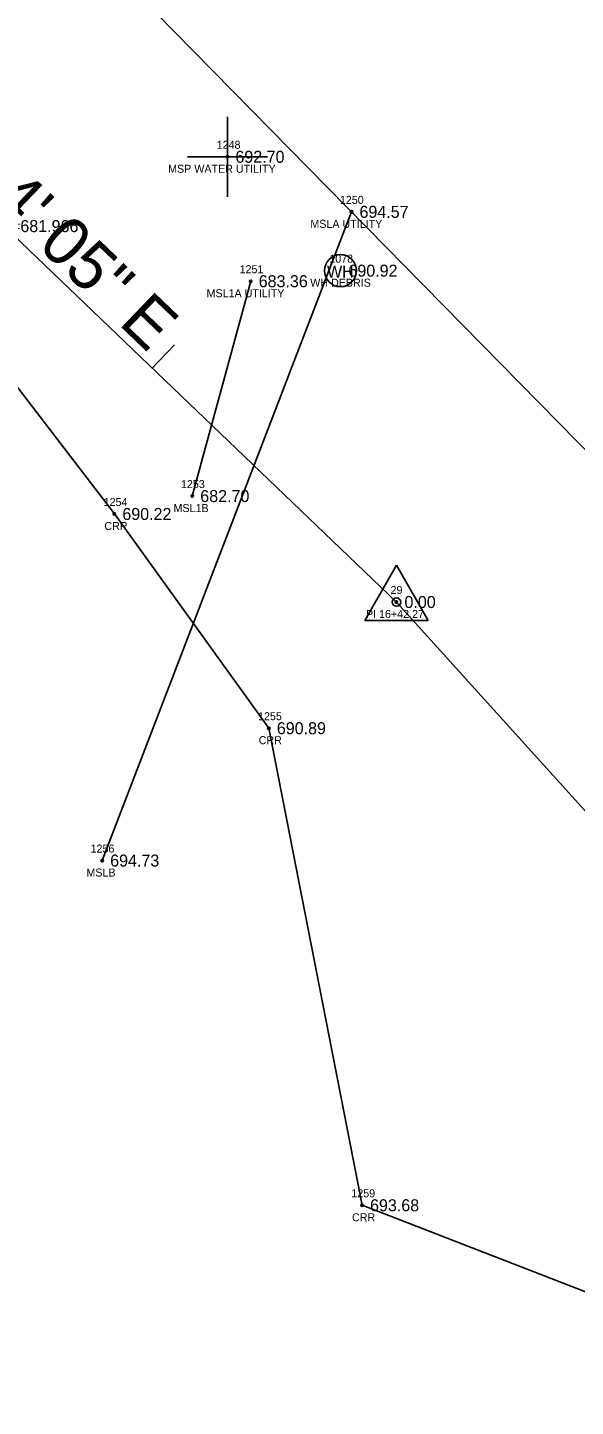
# Model space of a CAD drawing. Extents: x 1736563 to 1738032, y 1150548 to 1154248.
# Drawn here: x 1737439.5 to 1737508, y 1152510.8 to 1152683.1 of the extents above; entities that cross this region are included whole.
import ezdxf

# ---------------------------------------------------------------- set-up
doc = ezdxf.new("R2010")
doc.units = 0
for name, color, linetype in [('RD_EX_DV_PropPin', 7, 'Continuous'), ('RD_EX_H2O', 7, 'Continuous'), ('RD_EX_H2O_txCode', 7, 'Continuous'), ('RD_EX_Misc', 7, 'Continuous'), ('RD_EX_Misc_txCode', 7, 'Continuous'), ('RD_EX_SU_Misc_TxCode', 7, 'Continuous'), ('RD_EX_TX_H2O_ELEV', 7, 'Continuous'), ('RD_EX_TX_Misc_ELEV', 7, 'Continuous'), ('RD_HC_Cl', 7, 'Continuous'), ('RD_HC_Data', 7, 'Continuous'), ('RD_HC_Data_Tic', 7, 'Continuous'), ('RD_HC_Survey_ELEV', 7, 'Continuous'), ('RD_HC_txCode', 7, 'Continuous'), ('RD_SMD_Locator', 7, 'Continuous')]:
    doc.layers.add(name, color=color, linetype=linetype)

msp = doc.modelspace()

# ---------------------------------------------------------------- linework, layer by layer
at = {"layer": 'RD_EX_DV_PropPin'}
msp.add_circle((1737478.65, 1152652.71), 2, dxfattribs=at)
at = {"layer": 'RD_EX_H2O'}
for points in [[(1737441.68, 1152693.88), (1737445.94, 1152694.75), (1737513.08, 1152626.45), (1737553.92, 1152572.92), (1737629.09, 1152489.23), (1737700.8, 1152421.73), (1737779.1, 1152356.49), (1737820.92, 1152328.76)], [(1737416.87, 1152657.43), (1737429.45, 1152649.61), (1737450.39, 1152622.3), (1737469.7, 1152595.53), (1737481.35, 1152535.91), (1737513.9, 1152523.3), (1737579.93, 1152459.05), (1737654.23, 1152384.64), (1737738.06, 1152318.16), (1737784.96, 1152282.34)]]:
    msp.add_lwpolyline(points, dxfattribs=at)
at = {"layer": 'RD_EX_Misc'}
for p, q in [((1737464.52, 1152661.94), (1737464.52, 1152671.94)), ((1737459.52, 1152666.94), (1737469.52, 1152666.94)), ((1737480.03, 1152660.06), (1737448.87, 1152578.99)), ((1737467.43, 1152651.39), (1737460.13, 1152624.54))]:
    msp.add_line(p, q, dxfattribs=at)
at = {"layer": 'RD_EX_SU_Misc_TxCode'}
msp.add_circle((1737478.65, 1152652.71), 0.005, dxfattribs=at)
at = {"layer": 'RD_HC_Cl'}
for p, q in [((1737384.75, 1152707.94), (1737485.65, 1152611.3)), ((1737485.65, 1152611.3), (1737588.93, 1152496.85))]:
    msp.add_line(p, q, dxfattribs=at)
at = {"layer": 'RD_HC_Data'}
for p, q in [((1737481.68, 1152609.01), (1737485.65, 1152615.89)), ((1737485.65, 1152615.89), (1737489.62, 1152609.01)), ((1737481.68, 1152609.01), (1737489.62, 1152609.01))]:
    msp.add_line(p, q, dxfattribs=at)
msp.add_circle((1737485.65, 1152611.3), 0.529, dxfattribs=at)
at = {"layer": 'RD_HC_Data_Tic'}
msp.add_line((1737455.12, 1152640.54), (1737457.89, 1152643.43), dxfattribs=at)
at = {"layer": 'RD_SMD_Locator'}
for centre in [(1737464.52, 1152666.94), (1737480.03, 1152660.06), (1737467.43, 1152651.39), (1737460.13, 1152624.54), (1737450.39, 1152622.3), (1737485.65, 1152611.3), (1737469.7, 1152595.53), (1737448.87, 1152578.99), (1737481.35, 1152535.91)]:
    msp.add_circle(centre, 0.15, dxfattribs=at)

# ---------------------------------------------------------------- texts
at = {"layer": 'RD_EX_DV_PropPin'}
msp.add_text('WH', height=1.5, dxfattribs=at).set_placement((1737476.97, 1152651.83))
at = {"layer": 'RD_EX_H2O_txCode'}
for s, p in [('1078', (1737477.26, 1152653.71)), ('WH DEBRIS', (1737474.87, 1152650.71)), ('1254', (1737449.05, 1152623.3)), ('CRR', (1737449.14, 1152620.3)), ('1255', (1737468.35, 1152596.53)), ('CRR', (1737468.44, 1152593.53)), ('1259', (1737480.01, 1152536.91)), ('CRR', (1737480.1, 1152533.91))]:
    msp.add_text(s, height=1, dxfattribs=at).set_placement(p)
at = {"layer": 'RD_EX_Misc_txCode'}
for s, p in [('1248', (1737463.18, 1152667.94)), ('MSP WATER UTILITY', (1737457.11, 1152664.94)), ('1250', (1737478.58, 1152661.06)), ('MSLA UTILITY', (1737474.89, 1152658.06)), ('1251', (1737466.04, 1152652.39)), ('MSL1A UTILITY', (1737461.92, 1152649.39)), ('1253', (1737458.72, 1152625.54)), ('MSL1B', (1737457.79, 1152622.54)), ('1256', (1737447.42, 1152579.99)), ('MSLB', (1737446.9, 1152576.99))]:
    msp.add_text(s, height=1, dxfattribs=at).set_placement(p)
at = {"layer": 'RD_EX_TX_H2O_ELEV'}
for s, p in [('EL=681.966', (1737435.02, 1152657.53)), ('690.92', (1737479.65, 1152651.96)), ('690.22', (1737451.39, 1152621.55)), ('690.89', (1737470.7, 1152594.78)), ('693.68', (1737482.35, 1152535.16))]:
    msp.add_text(s, height=1.5, dxfattribs=at).set_placement(p)
at = {"layer": 'RD_EX_TX_Misc_ELEV'}
for s, p in [('692.70', (1737465.52, 1152666.19)), ('694.57', (1737481.03, 1152659.31)), ('683.36', (1737468.43, 1152650.64)), ('682.70', (1737461.13, 1152623.79)), ('694.73', (1737449.87, 1152578.24))]:
    msp.add_text(s, height=1.5, dxfattribs=at).set_placement(p)
at = {"layer": 'RD_HC_Data'}
msp.add_text('S 46%%d 14\' 05" E', height=6, rotation=316.2346, dxfattribs=at).set_placement((1737415.67, 1152679.71))
at = {"layer": 'RD_HC_Survey_ELEV'}
msp.add_text('0.00', height=1.5, dxfattribs=at).set_placement((1737486.65, 1152610.55))
at = {"layer": 'RD_HC_txCode'}
for s, p in [('29', (1737484.91, 1152612.3)), ('PI 16+42.27', (1737481.84, 1152609.3))]:
    msp.add_text(s, height=1, dxfattribs=at).set_placement(p)

doc.saveas('drawing.dxf')
